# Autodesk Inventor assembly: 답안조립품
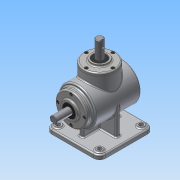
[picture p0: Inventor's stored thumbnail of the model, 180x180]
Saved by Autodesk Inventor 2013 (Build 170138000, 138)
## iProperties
Created: 2015-07
Part Number: 답안조립품
Document SubType Name: Assembly
Designer: Administrator
Author: Administrator
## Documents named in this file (14)
- C:\Users\Administrator\Desktop\450706V1020\답안조립품.iam
- C:\Users\Administrator\Desktop\450706V1020\1-본체.ipt
- C:\Users\Administrator\Desktop\450706V1020\커버.ipt
- C:\Users\Administrator\Desktop\450706V1020\베어링 6203.ipt
- C:\Users\Administrator\Desktop\450706V1020\오일실.ipt
- C:\Users\Administrator\Desktop\450706V1020\M4.ipt
- C:\Users\Administrator\Desktop\450706V1020\메인 축.ipt
- 메인 축.ipt
- C:\Users\Administrator\Desktop\450706V1020\키 5x5.ipt
- C:\Users\Administrator\Desktop\450706V1020\메인 베벨기어.ipt
- C:\Users\Administrator\Desktop\450706V1020\서브 축.ipt
- 서브 축.ipt
- C:\Users\Administrator\Desktop\450706V1020\키 4x4.ipt
- C:\Users\Administrator\Desktop\450706V1020\서브 베벨기어.ipt
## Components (9 placed, 2 different names)
1. 1-본체:1
2. M4:1
3. M4:2
4. M4:3
5. M4:4
6. M4:5
7. M4:6
8. M4:7
9. M4:8
